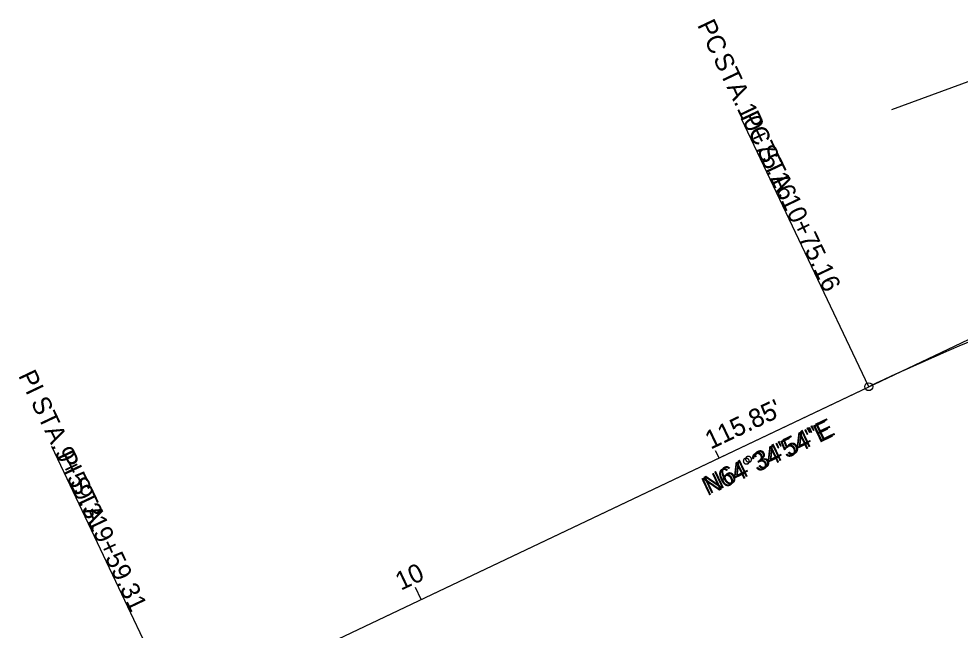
# Model space of a CAD drawing. Extents: x 219353 to 221640, y 361458 to 364236.
# Drawn here: x 220214 to 220356.8, y 362065.1 to 362157.8 of the extents above; entities that cross this region are included whole.
import ezdxf

# ---------------------------------------------------------------- set-up
doc = ezdxf.new("R2010")
doc.units = 0
for name, color, linetype in [('DR_P_Cells', 7, 'Continuous'), ('DR_P_GenericNode', 7, 'Continuous'), ('DR_X_Cells', 7, 'Continuous'), ('DT_X_Contour_Major', 7, 'Continuous'), ('DT_X_Contour_Minor', 7, 'Continuous'), ('SC_ProfileRun1', 7, 'Continuous'), ('SC_ProfileRun2', 7, 'Continuous'), ('SC_ProfileRun3', 7, 'Continuous'), ('SC_Scratch1', 7, 'Continuous'), ('UT_X_Sanitary_Cells', 7, 'Continuous')]:
    doc.layers.add(name, color=color, linetype=linetype)

msp = doc.modelspace()

# ---------------------------------------------------------------- linework, layer by layer
at = {"layer": 'DR_X_Cells'}
for p, q in [((220342.97, 362102.03), (220323.66, 362142.67)), ((220238.34, 362052.3), (220219.02, 362092.94))]:
    msp.add_line(p, q, dxfattribs=at)
msp.add_circle((220342.97, 362102.03), 0.6, dxfattribs=at)
at = {"layer": 'DT_X_Contour_Major'}
for q in [(220361, 362110.59), (220342.97, 362102.03), (220342.97, 362102.03)]:
    msp.add_line((220238.34, 362052.3), q, dxfattribs=at)
msp.add_arc((220493.2, 361785.91), 350, 108.8911, 115.4184, dxfattribs=at)
msp.add_arc((220493.2, 361785.91), 350, 108.8911, 115.4184, dxfattribs=at)
at = {"layer": 'DT_X_Contour_Minor'}
msp.add_line((220346.48, 362144.09), (220380.13, 362156.46), dxfattribs=at)
at = {"layer": 'SC_ProfileRun2'}
for p, q in [((220342.97, 362102.03), (220323.66, 362142.67)), ((220238.34, 362052.3), (220219.02, 362092.94))]:
    msp.add_line(p, q, dxfattribs=at)
msp.add_circle((220342.97, 362102.03), 0.6, dxfattribs=at)
at = {"layer": 'SC_ProfileRun3'}
msp.add_line((220275.09, 362069.77), (220274.23, 362071.57), dxfattribs=at)
at = {"layer": 'UT_X_Sanitary_Cells'}
for p, q in [((220320.25, 362091.23), (220319.74, 362092.31)), ((220275.09, 362069.77), (220274.23, 362071.57))]:
    msp.add_line(p, q, dxfattribs=at)

# ---------------------------------------------------------------- texts
at = {"layer": 'DR_P_Cells'}
msp.add_text("115.85'", height=2.8, rotation=25.4184, dxfattribs=at).set_placement((220319, 362092.47))
at = {"layer": 'DR_P_GenericNode'}
msp.add_text("115.85'", height=2.8, rotation=25.4184, dxfattribs=at).set_placement((220318.99, 362092.5))
at = {"layer": 'DR_X_Cells'}
for s, p in [('PC', (220323.53, 362143.04)), (' STA. ', (220325.5, 362138.9)), ('10+75.16', (220329.56, 362130.36)), ('PI', (220219.72, 362091.57)), (' STA. ', (220221.18, 362088.51)), ('9+59.31', (220225.23, 362079.97))]:
    msp.add_text(s, height=2.8, rotation=295.4184, dxfattribs=at).set_placement(p)
at = {"layer": 'SC_ProfileRun1'}
msp.add_text('N64°34\'54"E', height=2.8, rotation=25.4184, dxfattribs=at).set_placement((220318.83, 362085.7))
at = {"layer": 'SC_ProfileRun2'}
for s, p in [('PC', (220316.89, 362156.91)), (' STA. ', (220318.86, 362152.77)), ('10+75.16', (220322.91, 362144.24)), ('PI', (220213.9, 362103.72)), (' STA. ', (220215.36, 362100.65)), ('9+59.31', (220219.42, 362092.12))]:
    msp.add_text(s, height=2.8, rotation=295.4184, dxfattribs=at).set_placement(p)
at = {"layer": 'SC_ProfileRun3'}
msp.add_text('10', height=2.8, rotation=25.4184, dxfattribs=at).set_placement((220272, 362071.07))
at = {"layer": 'SC_Scratch1'}
msp.add_text('N64°34\'54"E', height=2.8, rotation=25.4184, dxfattribs=at).set_placement((220318.49, 362085.41))
at = {"layer": 'UT_X_Sanitary_Cells'}
msp.add_text('10', height=2.8, rotation=25.4184, dxfattribs=at).set_placement((220272, 362071.07))

doc.saveas('drawing.dxf')
